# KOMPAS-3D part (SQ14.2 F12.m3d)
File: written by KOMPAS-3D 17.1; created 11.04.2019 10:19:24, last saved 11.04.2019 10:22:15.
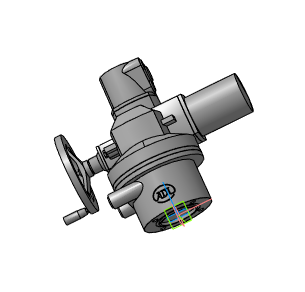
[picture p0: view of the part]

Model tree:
1. Операция без истории:4
2. Эскиз:2
3. Элемент выдавливания:2
     Расстояние 2 = 60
